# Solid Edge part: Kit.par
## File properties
Sűrűség: 0,000 kg/m^3
Pontosság: 0,990
Author: ahadarics
Last saved by: ahadarics
Revision: 77
Username: ahadarics
Dokumentum tartalom típus: 0
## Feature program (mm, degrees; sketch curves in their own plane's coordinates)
base feature "unnamed BaseFeature 1"
sketch for "Furat_1" plane through (0, -48.5, 12) normal (0, 0, 1) x-axis (0, 1, 0)
  hole centre (-0.25, 0) bore radius 4.283
hole "Furat_1" nominal diameter 9.728 finite  ThreadDepth = 7.5 mm
chamfer "Letörés_1" setback 0.7
thread "unnamed Thread 1"
chamfer "Letörés_2" setback 1.5
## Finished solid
Body 1: solid body, 49 faces, 54 edges, 8 vertices.
  Faces by surface: plane 15, cylinder 14, cone 13, torus 7
  Edges by curve: circle 46, intersection 4, line 4
Bounding box of the edges (mm; curved faces can reach further): 27.000 x 37.500 x 25.500, from (-13.5, -76.25, -13.5) to (13.5, -38.75, 12).
Cylindrical faces by radius (mm): R4.15 x1, R4.25 x1, R4.28 x1, R4.283 x1, R4.55 x1, R6 x1, R6.05 x1, R7.05 x1, R7.1 x1, R9.85 x1, R11 x2, R11.1 x1, R13.5 x1
Conical faces (half-angle, radius in mm at the cone's reference point): 0.1788 deg R5.7706 x1, 15 deg R7.05 x1, 19.7315 deg R4.0176 x1, 20.542 deg R4.55 x1, 21.5244 deg R5.2703 x1, 24.3997 deg R4.55 x1, 45 deg R4.983 x1, 45 deg R6.15 x1, 45 deg R6.2 x1, 45 deg R11 x1, 59 deg R2.1415 x2, 60 deg R10.425 x1
Toroidal faces (ring radius, tube radius in mm): R4.2 r0.2 x1, R4.3 r0.3 x1, R5.6424 r0.4 x1, R5.85 r0.2 x1, R6.85 r0.2 x1, R6.9 r0.2 x2
Planar faces by outward normal: +y 5, +z 2, -y 8
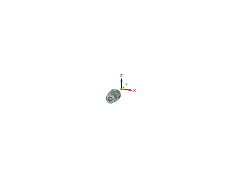
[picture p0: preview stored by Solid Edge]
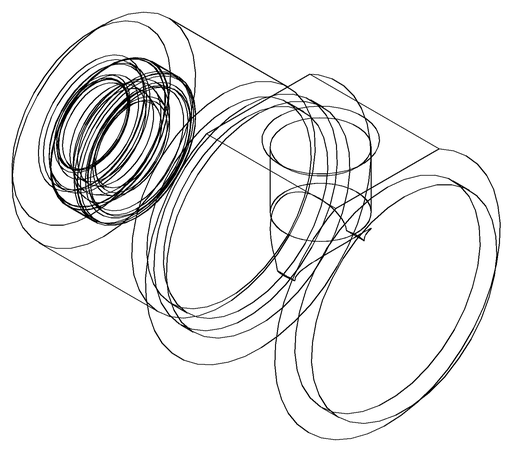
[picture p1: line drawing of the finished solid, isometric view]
